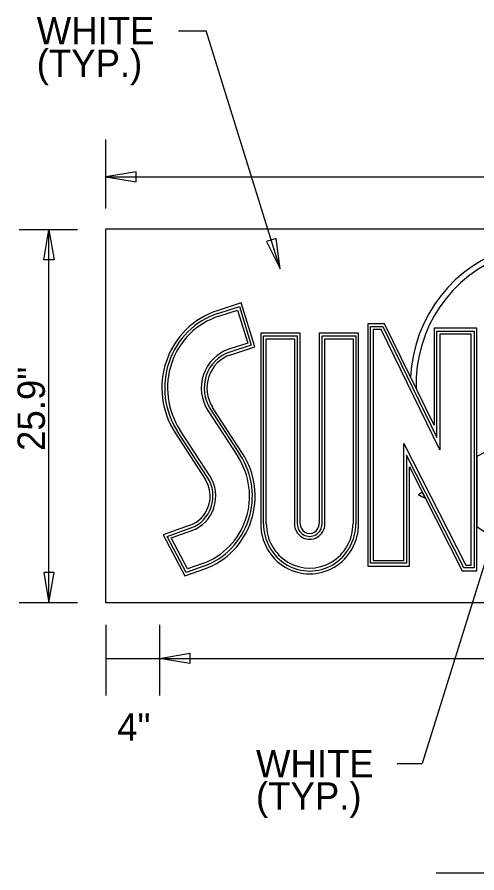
# Model space of a CAD drawing. Extents: x 10268197 to 10268738, y 2141503 to 2142677.
# Drawn here: x 10268672.51 to 10268684.28, y 2142399.46 to 2142421.36 of the extents above; entities that cross this region are included whole.
import ezdxf

# ---------------------------------------------------------------- set-up
doc = ezdxf.new("R2010")
doc.units = 0
for name, color, linetype in [('1', 7, 'Continuous'), ('Default', 7, 'Continuous'), ('GSDims', 7, 'Continuous')]:
    doc.layers.add(name, color=color, linetype=linetype)

msp = doc.modelspace()

# ---------------------------------------------------------------- linework, layer by layer
at = {"layer": '1'}
for p, q in [((10268676.642, 2142421.01), (10268677.345, 2142421.01)), ((10268679.246, 2142414.92), (10268677.345, 2142421.01)), ((10268684.729, 2142408.184), (10268682.878, 2142402.256)), ((10268700.725, 2142406.37), (10268674.779, 2142406.37)), ((10268682.239, 2142402.256), (10268682.878, 2142402.256))]:
    msp.add_line(p, q, dxfattribs=at)
at = {"layer": 'Default'}
for p, q in [((10268677.65, 2142413.776), (10268678.197, 2142413.953)), ((10268677.671, 2142413.705), (10268678.15, 2142413.86)), ((10268677.671, 2142413.705), (10268678.15, 2142413.86)), ((10268678.15, 2142413.86), (10268678.411, 2142413.015)), ((10268678.15, 2142413.86), (10268678.411, 2142413.015)), ((10268678.197, 2142413.953), (10268678.501, 2142412.966)), ((10268681.484, 2142413.514), (10268681.484, 2142407.307)), ((10268681.556, 2142407.381), (10268681.556, 2142413.44)), ((10268678.816, 2142408.395), (10268678.816, 2142413.199)), ((10268678.816, 2142413.199), (10268679.681, 2142413.199)), ((10268679.681, 2142413.199), (10268679.681, 2142408.396)), ((10268680.315, 2142408.396), (10268680.315, 2142413.199)), ((10268680.315, 2142413.199), (10268681.18, 2142413.199)), ((10268681.18, 2142413.199), (10268681.18, 2142408.395)), ((10268681.628, 2142413.366), (10268681.628, 2142407.455)), ((10268681.828, 2142413.366), (10268681.628, 2142413.366)), ((10268683.33, 2142410.287), (10268681.828, 2142413.366)), ((10268683.33, 2142413.248), (10268683.33, 2142410.287)), ((10268684.137, 2142413.248), (10268683.33, 2142413.248)), ((10268684.137, 2142407.336), (10268684.137, 2142413.248)), ((10268678.411, 2142413.015), (10268677.932, 2142412.86)), ((10268678.411, 2142413.015), (10268677.932, 2142412.86)), ((10268678.501, 2142412.966), (10268677.953, 2142412.789)), ((10268678.888, 2142408.396), (10268678.888, 2142413.125)), ((10268678.888, 2142413.125), (10268679.609, 2142413.125)), ((10268678.888, 2142408.396), (10268678.888, 2142413.125)), ((10268678.888, 2142413.125), (10268679.609, 2142413.125)), ((10268679.609, 2142413.125), (10268679.609, 2142408.396)), ((10268679.609, 2142413.125), (10268679.609, 2142408.396)), ((10268680.388, 2142408.396), (10268680.388, 2142413.125)), ((10268680.388, 2142413.125), (10268681.108, 2142413.125)), ((10268680.388, 2142408.396), (10268680.388, 2142413.125)), ((10268680.388, 2142413.125), (10268681.108, 2142413.125)), ((10268681.108, 2142413.125), (10268681.108, 2142408.396)), ((10268681.108, 2142413.125), (10268681.108, 2142408.396)), ((10268682.584, 2142412.147), (10268682.725, 2142411.857)), ((10268677.393, 2142411.291), (10268678.16, 2142410.111)), ((10268677.393, 2142411.291), (10268678.16, 2142410.111)), ((10268677.453, 2142411.332), (10268678.22, 2142410.152)), ((10268678.28, 2142410.193), (10268677.513, 2142411.373)), ((10268677.44, 2142409.619), (10268676.673, 2142410.799)), ((10268677.44, 2142409.619), (10268676.673, 2142410.799)), ((10268676.553, 2142410.717), (10268677.32, 2142409.537)), ((10268677.38, 2142409.578), (10268676.613, 2142410.758)), ((10268682.407, 2142407.455), (10268682.407, 2142410.451)), ((10268682.407, 2142410.451), (10268683.994, 2142407.336)), ((10268684.281, 2142410.111), (10268684.281, 2142408.31)), ((10268682.962, 2142409.043), (10268682.881, 2142409.202)), ((10268676.352, 2142408.071), (10268676.957, 2142408.287)), ((10268676.455, 2142408.03), (10268676.981, 2142408.217)), ((10268676.455, 2142408.03), (10268676.981, 2142408.217)), ((10268676.833, 2142407.147), (10268676.352, 2142408.071)), ((10268676.867, 2142407.238), (10268676.455, 2142408.03)), ((10268676.867, 2142407.238), (10268676.455, 2142408.03)), ((10268677.289, 2142407.31), (10268676.833, 2142407.147)), ((10268677.265, 2142407.379), (10268676.867, 2142407.238)), ((10268677.265, 2142407.379), (10268676.867, 2142407.238)), ((10268681.628, 2142407.455), (10268682.407, 2142407.455)), ((10268683.994, 2142407.336), (10268684.137, 2142407.336)), ((10268700.725, 2142406.37), (10268674.779, 2142406.37)), ((10268683.234, 2142399.458), (10268693.665, 2142399.458))]:
    msp.add_line(p, q, dxfattribs=at)
for points in [[(10268674.779, 2142406.37), (10268674.779, 2142415.938), (10268700.725, 2142415.938), (10268700.725, 2142406.37)], [(10268677.975, 2142412.719), (10268678.592, 2142412.918), (10268678.244, 2142414.046), (10268677.628, 2142413.846)], [(10268681.484, 2142407.307), (10268682.551, 2142407.307), (10268682.551, 2142409.849), (10268683.906, 2142407.189), (10268684.281, 2142407.189), (10268684.281, 2142413.396), (10268683.185, 2142413.396), (10268683.185, 2142410.913), (10268681.917, 2142413.514), (10268681.484, 2142413.514)], [(10268681.556, 2142413.44), (10268681.872, 2142413.44), (10268683.257, 2142410.6), (10268683.257, 2142413.322), (10268684.209, 2142413.322), (10268684.209, 2142407.262), (10268683.95, 2142407.262), (10268682.479, 2142410.15), (10268682.479, 2142407.381), (10268681.556, 2142407.381)], [(10268679.753, 2142408.396), (10268679.753, 2142413.272), (10268678.744, 2142413.272), (10268678.744, 2142408.396)], [(10268681.252, 2142408.396), (10268681.252, 2142413.272), (10268680.243, 2142413.272), (10268680.243, 2142408.396)], [(10268676.934, 2142408.357), (10268676.249, 2142408.112), (10268676.798, 2142407.057), (10268677.312, 2142407.24)]]:
    msp.add_lwpolyline(points, dxfattribs=at)
msp.add_lwpolyline([(10268683.33, 2142413.248), (10268683.33, 2142410.287), (10268681.828, 2142413.366), (10268681.628, 2142413.366), (10268681.628, 2142407.455), (10268682.407, 2142407.455), (10268682.407, 2142410.451), (10268683.994, 2142407.336), (10268684.137, 2142407.336), (10268684.137, 2142413.248)], close=True, dxfattribs=at)
for centre, major_axis, ratio, start_param, end_param in [((10268686.111, 2142411.962), (0, 3.62), 0.97582, 5.303349, 7.802858), ((10268686.111, 2142411.962), (0, 3.62), 0.97582, 5.303349, 7.802858), ((10268686.111, 2142411.962), (0, 3.472), 0.97582, 5.332201, 7.884008), ((10268686.111, 2142411.962), (0, 3.472), 0.97582, 5.332201, 7.884008), ((10268678.238, 2142411.868), (0, 2.075), 0.97582, 0.306207, 2.15869), ((10268678.238, 2142411.868), (0, 2.001), 0.97582, 0.306207, 2.15869), ((10268678.237, 2142411.868), (0, 1.927), 0.975477, 0.305879, 2.158799), ((10268678.237, 2142411.868), (0, 1.927), 0.975477, 0.305879, 2.158799), ((10268678.237, 2142411.868), (0, 1.04), 0.975477, 0.305879, 2.158799), ((10268678.237, 2142411.868), (0, 1.04), 0.975477, 0.305879, 2.158799), ((10268678.238, 2142411.868), (0, 0.966), 0.97582, 0.306207, 2.15869), ((10268678.238, 2142411.868), (0, 0.892), 0.97582, 0.306207, 2.15869), ((10268686.111, 2142411.96), (0, -3.472), 0.97582, 4.712389, 4.712389), ((10268689.687, 2142399.778), (0, 11.724), 0.97582, 0.138501, 0.492135), ((10268689.687, 2142399.778), (0, 11.724), 0.97582, 0.138501, 0.492135), ((10268676.68, 2142409.101), (0, 1.896), 0.97582, 3.476656, 5.300276), ((10268676.68, 2142409.101), (0, 1.97), 0.97582, 3.476656, 5.300276), ((10268676.681, 2142409.101), (0, -1.822), 0.975477, 0.334737, 2.158799), ((10268676.681, 2142409.101), (0, -1.822), 0.975477, 0.334737, 2.158799), ((10268676.681, 2142409.101), (0, 0.788), 0.97582, 3.476661, 5.300276), ((10268676.681, 2142409.101), (0, 0.862), 0.97582, 3.476661, 5.300276), ((10268676.681, 2142409.101), (0, -0.935), 0.975477, 0.334742, 2.158799), ((10268676.681, 2142409.101), (0, -0.935), 0.975477, 0.334742, 2.158799), ((10268689.687, 2142399.778), (0, 11.724), 0.97582, 0.637151, 0.647654), ((10268689.687, 2142399.778), (0, 11.724), 0.97582, 0.637152, 0.647654), ((10268676.659, 2142395.507), (0, 14.998), 0.97582, 5.837989, 5.851358), ((10268676.659, 2142395.507), (0, 14.998), 0.97582, 5.837989, 5.851358), ((10268679.998, 2142408.395), (0, 1.285), 0.97582, 1.570446, 4.71274), ((10268679.998, 2142408.395), (0, 1.211), 0.97582, 1.570446, 4.71274), ((10268679.998, 2142408.396), (0, -1.138), 0.975477, 4.712389, 7.853982), ((10268679.998, 2142408.396), (0, -1.138), 0.975477, 4.712389, 7.853982), ((10268679.998, 2142408.396), (0, -0.399), 0.975477, 4.712389, 7.853982), ((10268679.998, 2142408.396), (0, -0.399), 0.975477, 4.712389, 7.853982), ((10268679.998, 2142408.395), (0, 0.325), 0.97582, 1.570446, 4.71274), ((10268679.998, 2142408.395), (0, 0.251), 0.97582, 1.570446, 4.71274), ((10268676.659, 2142395.507), (0, 14.998), 0.97582, 5.556667, 5.735414), ((10268676.659, 2142395.507), (0, 14.998), 0.97582, 5.556667, 5.735414)]:
    msp.add_ellipse(centre, major_axis=major_axis, ratio=ratio, start_param=start_param, end_param=end_param, dxfattribs=at)
at = {"layer": 'GSDims'}
for p, q in [((10268674.779, 2142416.464), (10268674.779, 2142418.232)), ((10268674.779, 2142417.271), (10268700.725, 2142417.271)), ((10268674.053, 2142415.918), (10268672.562, 2142415.918)), ((10268673.322, 2142406.37), (10268673.322, 2142415.918)), ((10268674.053, 2142406.37), (10268672.562, 2142406.37)), ((10268674.779, 2142405.805), (10268674.779, 2142404.002)), ((10268676.151, 2142405.805), (10268676.151, 2142404.002)), ((10268674.779, 2142404.948), (10268676.151, 2142404.948)), ((10268676.151, 2142404.948), (10268699.386, 2142404.948))]:
    msp.add_line(p, q, dxfattribs=at)
for points in [[(10268674.779, 2142417.271), (10268675.553, 2142417.142), (10268675.553, 2142417.4)], [(10268673.322, 2142415.918), (10268673.452, 2142415.144), (10268673.193, 2142415.144)], [(10268679.246, 2142414.92), (10268679.138, 2142415.698), (10268678.892, 2142415.621)], [(10268673.322, 2142406.37), (10268673.452, 2142407.145), (10268673.193, 2142407.145)], [(10268676.151, 2142404.948), (10268676.925, 2142405.078), (10268676.925, 2142404.819)]]:
    msp.add_lwpolyline(points, close=True, dxfattribs=at)

# ---------------------------------------------------------------- texts
at = {"layer": '1'}
for s, p in [('WHITE', (10268673.007, 2142420.66)), ('(TYP.)', (10268673.007, 2142419.829)), ('4"', (10268675.068, 2142402.84)), ('WHITE', (10268678.623, 2142401.906)), ('(TYP.)', (10268678.623, 2142401.075))]:
    msp.add_text(s, height=0.7, dxfattribs=at).set_placement(p)
msp.add_text('25.9"', height=0.7, rotation=90, dxfattribs=at).set_placement((10268673.216, 2142410.257))

doc.saveas('drawing.dxf')
